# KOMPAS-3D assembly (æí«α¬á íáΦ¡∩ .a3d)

Referenced files in D:\МОДЕЛЬ ТАНКА Т90\ДЕТАЛИ\БАШНЯ\башня сварная\: Сборка бшня низ со стволом.a3d, башня верх.m3d, прибор2.m3d, антена.m3d, лазер1.m3d, лазер2.m3d, датчик ветра.m3d
Referenced files in D:\МОДЕЛЬ ТАНКА Т90\ДЕТАЛИ\БАШНЯ\башня сварная\НАВЕСКА\: ДЗ башни.m3d, Сборка ДЗ башни3.a3d, Сборка ДЗ башни5.a3d, прибор1.m3d, Сборка ящик левый.a3d, Сборка ящик правый.a3d, Сборка ящик.a3d, Сборка туча левая.a3d, Сборка туча правая.a3d, Сборка туча левая верхняя.a3d
Referenced files in D:\МОДЕЛЬ ТАНКА Т90\ДЕТАЛИ\ОБЩИЕ ДЕТАЛИ\: стоп задний.m3d
Referenced files in D:\МОДЕЛЬ ТАНКА Т90\СБОРКИ\сборка фара правая\: фара задняя.m3d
